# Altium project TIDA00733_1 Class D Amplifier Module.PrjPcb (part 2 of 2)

## Sheet TIDA00733_1 Class D Amp Sheet 6.SchDoc
size 431 x 279 mm; Date: Not shown in title block; ApprovedBy: Not shown in title block; CheckedBy: Not shown in title block; Author: Not shown in title block; CompanyName: Not shown in title block; Engineer: Not shown in title block; Organization: Not shown in title block; Address1: Not shown in title block; Address2: Not shown in title block; Address3: Not shown in title block; Address4: Not shown in title block; DocumentNumber: 6; Revision: Use project parameter SCH_Rev; SheetNumber: 6; SheetTotal: 8; PageSetup: Record=PageOptions¦CenterHorizontal=True¦CenterVertical=True¦PrintScale=1.00¦XCorrection=1.00¦YCorrection=1.00¦PrintKind=0¦BorderSize=5000000¦LeftOffset=0¦BottomOffset=0¦Orientation=2¦PaperLength=1000¦PaperWidth=1000¦Scale=100¦PaperSource=15¦PrintQuality=600¦MediaType=1¦DitherType=10¦PaperKind=Letter¦PrintScaleMode=1
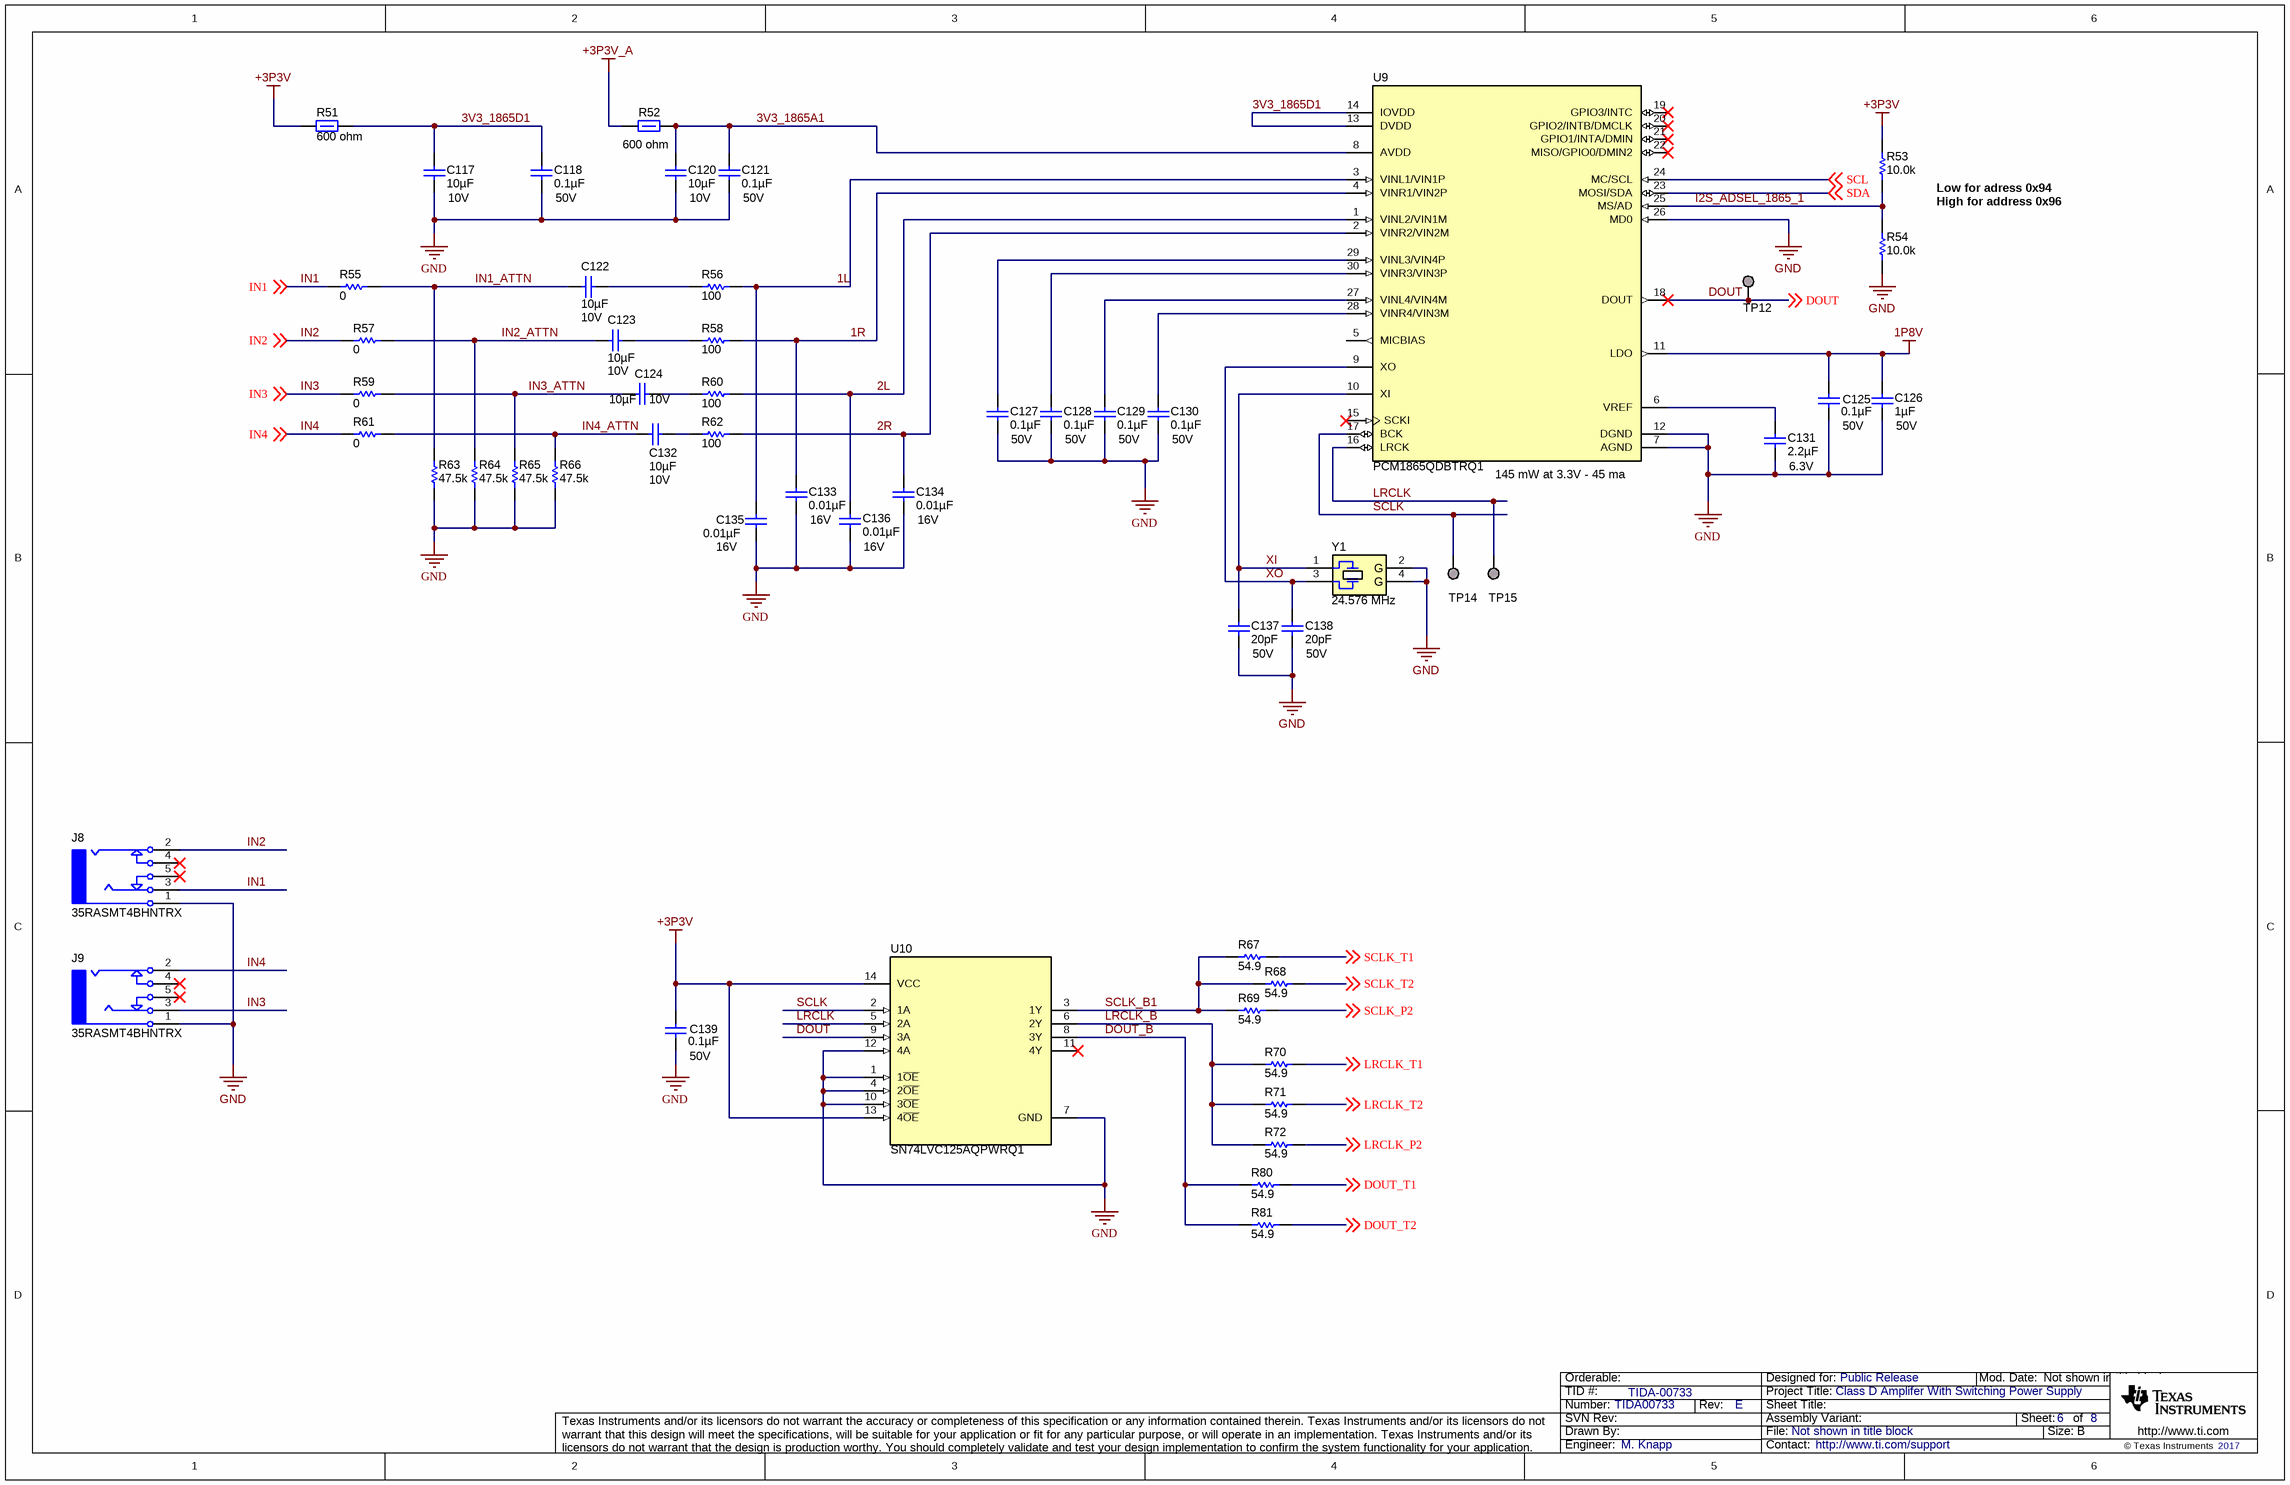
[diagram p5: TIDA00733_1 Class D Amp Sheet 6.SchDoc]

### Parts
C117  ValueDisplayed: 10µF  Value2: 10V  [0805L]  (hidden comment: GRM21BR71A106KE51L)
C118  ValueDisplayed: 0.1µF  Value2: 50V  [0402L]  (hidden comment: C1005X7R1H104K050BB)
C120  ValueDisplayed: 10µF  Value2: 10V  [0805L]  (hidden comment: GRM21BR71A106KE51L)
C121  ValueDisplayed: 0.1µF  Value2: 50V  [0402L]  (hidden comment: C1005X7R1H104K050BB)
C122  ValueDisplayed: 10µF  Value2: 10V  [0805L]  (hidden comment: GRM21BR71A106KE51L)
C123  ValueDisplayed: 10µF  Value2: 10V  [0805L]  (hidden comment: GRM21BR71A106KE51L)
C124  ValueDisplayed: 10µF  Value2: 10V  [0805L]  (hidden comment: GRM21BR71A106KE51L)
C125  ValueDisplayed: 0.1µF  Value2: 50V  [0402L]  (hidden comment: C1005X7R1H104K050BB)
C126  ValueDisplayed: 1µF  Value2: 50V  [0805L]  (hidden comment: GRM21BR71H105KA12L)
C127  ValueDisplayed: 0.1µF  Value2: 50V  [0402L]  (hidden comment: C1005X7R1H104K050BB)
C128  ValueDisplayed: 0.1µF  Value2: 50V  [0402L]  (hidden comment: C1005X7R1H104K050BB)
C129  ValueDisplayed: 0.1µF  Value2: 50V  [0402L]  (hidden comment: C1005X7R1H104K050BB)
C130  ValueDisplayed: 0.1µF  Value2: 50V  [0402L]  (hidden comment: C1005X7R1H104K050BB)
C131  ValueDisplayed: 2.2µF  Value2: 6.3V  [0603L]  (hidden comment: GCM188R70J225KE22D)
C132  ValueDisplayed: 10µF  Value2: 10V  [0805L]  (hidden comment: GRM21BR71A106KE51L)
C133  ValueDisplayed: 0.01µF  Value2: 16V  [0402L]  (hidden comment: 885012205031)
C134  ValueDisplayed: 0.01µF  Value2: 16V  [0402L]  (hidden comment: 885012205031)
C135  ValueDisplayed: 0.01µF  Value2: 16V  [0402L]  (hidden comment: 885012205031)
C136  ValueDisplayed: 0.01µF  Value2: 16V  [0402L]  (hidden comment: 885012205031)
C137  ValueDisplayed: 20pF  Value2: 50V  [0402L]  (hidden comment: GRM1555C1H200JA01D)
C138  ValueDisplayed: 20pF  Value2: 50V  [0402L]  (hidden comment: GRM1555C1H200JA01D)
C139  ValueDisplayed: 0.1µF  Value2: 50V  [0402L]  (hidden comment: C1005X7R1H104K050BB)
J8  35RASMT4BHNTRX  [Switchcraft_35RASM]
J9  35RASMT4BHNTRX  [Switchcraft_35RASM]
R51  ValueDisplayed: 600 ohm  [0402L]  (hidden comment: BLM15AX601SN1D)
R52  ValueDisplayed: 600 ohm  [0402L]  (hidden comment: BLM15AX601SN1D)
R53  ValueDisplayed: 10.0k  [0402L]  (hidden comment: CRCW040210K0FKED)
R54  ValueDisplayed: 10.0k  [0402L]  (hidden comment: CRCW040210K0FKED)
R55  ValueDisplayed: 0  [0402L]  (hidden comment: CRCW04020000Z0ED)
R56  ValueDisplayed: 100  [0402L]  (hidden comment: CRCW0402100RFKED)
R57  ValueDisplayed: 0  [0402L]  (hidden comment: CRCW04020000Z0ED)
R58  ValueDisplayed: 100  [0402L]  (hidden comment: CRCW0402100RFKED)
R59  ValueDisplayed: 0  [0402L]  (hidden comment: CRCW04020000Z0ED)
R60  ValueDisplayed: 100  [0402L]  (hidden comment: CRCW0402100RFKED)
R61  ValueDisplayed: 0  [0402L]  (hidden comment: CRCW04020000Z0ED)
R62  ValueDisplayed: 100  [0402L]  (hidden comment: CRCW0402100RFKED)
R63  ValueDisplayed: 47.5k  [0402L]  (hidden comment: CRCW040247K5FKED)
R64  ValueDisplayed: 47.5k  [0402L]  (hidden comment: CRCW040247K5FKED)
R65  ValueDisplayed: 47.5k  [0402L]  (hidden comment: CRCW040247K5FKED)
R66  ValueDisplayed: 47.5k  [0402L]  (hidden comment: CRCW040247K5FKED)
R67  ValueDisplayed: 54.9  [0402L]  (hidden comment: CRCW040254R9FKED)
R68  ValueDisplayed: 54.9  [0402L]  (hidden comment: CRCW040254R9FKED)
R69  ValueDisplayed: 54.9  [0402L]  (hidden comment: CRCW040254R9FKED)
R70  ValueDisplayed: 54.9  [0402L]  (hidden comment: CRCW040254R9FKED)
R71  ValueDisplayed: 54.9  [0402L]  (hidden comment: CRCW040254R9FKED)
R72  ValueDisplayed: 54.9  [0402L]  (hidden comment: CRCW040254R9FKED)
R80  ValueDisplayed: 54.9  [0402L]  (hidden comment: CRCW040254R9FKED)
R81  ValueDisplayed: 54.9  [0402L]  (hidden comment: CRCW040254R9FKED)
TP12  TESTPOINT  [PAD_1MM_SQUARE]  (value not drawn)  (no BOM)
TP14  TESTPOINT  [PAD_1MM_SQUARE]  (value not drawn)  (no BOM)
TP15  TESTPOINT  [PAD_1MM_SQUARE]  (value not drawn)  (no BOM)
U9  PCM1865QDBTRQ1  [DBT0030A_N]
U10  SN74LVC125AQPWRQ1  [PW0014A_N]
Y1  Frequency_Fixed: 24.576 MHz  [Abracon_ABM10AIG]  (hidden comment: ABM10AIG-24.576MHZ-J4Z-T3)

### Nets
1P8V: C125.1 C126.1 U9.11(LDO)
+3P3V: C139.1 R51.2 R53.2 U10.13(4~{OE}) U10.14(VCC)
+3P3V_A: R52.2
GND: C117.2 C118.2 C120.2 C121.2 C125.2 C126.2 C127.2 C128.2 C129.2 C130.2 C131.2 C133.2 C134.2 C135.2 C136.2 C137.2 C138.2 C139.2 J8.1(SLEEVE) J9.1(SLEEVE) R54.1 R63.1 R64.1 R65.1 R66.1 U9.7(AGND) U9.12(DGND) U9.26(MD0) U10.1(1~{OE}) U10.4(2~{OE}) U10.7(GND) U10.10(3~{OE}) U10.12(4A) Y1.2(GND) Y1.4(GND)
1L: C135.1 R56.2 U9.3(VINL1/VIN1P)
1R: C133.1 R58.2 U9.4(VINR1/VIN2P)
2L: C136.1 R60.2 U9.1(VINL2/VIN1M)
2R: C134.1 R62.2 U9.2(VINR2/VIN2M)
3V3_1865A1: C120.1 C121.1 R52.1 U9.8(AVDD)
3V3_1865D1: C117.1 C118.1 R51.1 U9.13(DVDD) U9.14(IOVDD)
DOUT: TP12.1 U9.18(DOUT) U10.9(3A) ; off-sheet DOUT
DOUT_B: R80.1 R81.1 U10.8(3Y)
DOUT_T1: R80.2 ; off-sheet DOUT_T1
DOUT_T2: R81.2 ; off-sheet DOUT_T2
I2S_ADSEL_1865_1: R53.1 R54.2 U9.25(MS/AD)
IN1: J8.3(TIP) R55.2 ; off-sheet IN1
IN1_ATTN: C122.1 R55.1 R63.2
IN2: J8.2(RING) R57.2 ; off-sheet IN2
IN2_ATTN: C123.1 R57.1 R64.2
IN3: J9.3(TIP) R59.2 ; off-sheet IN3
IN3_ATTN: C124.1 R59.1 R65.2
IN4: J9.2(RING) R61.2 ; off-sheet IN4
IN4_ATTN: C132.1 R61.1 R66.2
LRCLK: TP15.1 U9.16(LRCK) U10.5(2A)
LRCLK_B: R70.1 R71.1 R72.1 U10.6(2Y)
LRCLK_P2: R72.2 ; off-sheet LRCLK_P2
LRCLK_T1: R70.2 ; off-sheet LRCLK_T1
LRCLK_T2: R71.2 ; off-sheet LRCLK_T2
SCL: U9.24(MC/SCL) ; off-sheet SCL
SCLK: TP14.1 U9.17(BCK) U10.2(1A)
SCLK_B1: R67.1 R68.1 R69.1 U10.3(1Y)
SCLK_P2: R69.2 ; off-sheet SCLK_P2
SCLK_T1: R67.2 ; off-sheet SCLK_T1
SCLK_T2: R68.2 ; off-sheet SCLK_T2
SDA: U9.23(MOSI/SDA) ; off-sheet SDA
XI: C137.1 U9.10(XI) Y1.1
XO: C138.1 U9.9(XO) Y1.3
NetC122_2: C122.2 R56.1
NetC123_2: C123.2 R58.1
NetC124_2: C124.2 R60.1
NetC127_1: C127.1 U9.29(VINL3/VIN4P)
NetC128_1: C128.1 U9.30(VINR3/VIN3P)
NetC129_1: C129.1 U9.27(VINL4/VIN4M)
NetC130_1: C130.1 U9.28(VINR4/VIN3M)
NetC131_1: C131.1 U9.6(VREF)
NetC132_2: C132.2 R62.1

Not connected (* = marked no-connect by the designer): J8 4(RING_SWITCH)* 5(TIP_SWITCH)*; J9 4(RING_SWITCH)* 5(TIP_SWITCH)*; U9 5(MICBIAS) 15(SCKI)* 19(GPIO3/INTC)* 20(GPIO2/INTB/DMCLK)* 21(GPIO1/INTA/DMIN)* 22(MISO/GPIO0/DMIN2)*; U10 11(4Y)*

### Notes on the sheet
- Low for adress 0x94
  High for address 0x96
- (near U9) 145 mW at 3.3V - 45 ma

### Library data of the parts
C117 C120 C122-C124 C132 = GRM21BR71A106KE51L: CAP, CERM, 10 µF, 10 V, +/- 10%, X7R, 0805; Manufacturer: MuRata; Polarized: N; CompType: Capacitor; Value: 10uF; U/M: EA; Cap_F: 0.00001; Tolerance_%: 10; ESR_ohm: 0.003; Value1: 0.003 ohm; TaMin_C: -55; TaMax_C: 125; Cap_Case: 0805; AEC Category: Q200; SizeArea_mm2: 2.5; SizeAreaWB_mm2: 6.75; SizeX_mm: 2; SizeY_mm: 1.25; SizeZ_mm: 1.45
C118 C121 C125 C127-C130 C139 = C1005X7R1H104K050BB: CAP, CERM, 0.1 µF, 50 V, +/- 10%, X7R, 0402; Manufacturer: TDK; Polarized: N; CompType: Capacitor; Value: 0.1uF; U/M: EA; Cap_F: 0.0000001; Tolerance_%: 10; ESR_ohm: 0.039064; Value1: 0.039064 ohm; VDC_V: 50; IRMS_A: 0.814669; TaMin_C: -55; TaMax_C: 125; Cap_Case: 0402; AEC Category: Q200; SizeArea_mm2: 0.5; SizeAreaWB_mm2: 3; SizeX_mm: 1; SizeZ_mm: 0.6
C126 = GRM21BR71H105KA12L: CAP, CERM, 1 µF, 50 V, +/- 10%, X7R, 0805; Manufacturer: MuRata; Polarized: N; CompType: Capacitor; Value: 1uF; U/M: EA; Cap_F: 0.000001; Tolerance_%: 10; Value1: Unknown; VDC_V: 50; TaMin_C: -55; TaMax_C: 125; Cap_Case: 0805; AEC Category: Q200; SizeArea_mm2: 2.5; SizeAreaWB_mm2: 6.75; SizeX_mm: 2; SizeY_mm: 1.25; SizeZ_mm: 1.45
C131 = GCM188R70J225KE22D: CAP, CERM, 2.2 µF, 6.3 V, +/- 10%, X7R, AEC-Q200 Grade 1, 0603; Manufacturer: MuRata; Polarized: N; CompType: Capacitor; Value: 2.2uF; U/M: EA; Cap_F: 0.0000022; Tolerance_%: 10; Value1: Unknown; VDC_V: 6.3; TaMin_C: -55; TaMax_C: 125; Cap_Case: 0603; AEC Category: Q200; AEC Qualified: Y; AEC Grade: 1; SizeArea_mm2: 1.28; SizeAreaWB_mm2: 4.68; SizeX_mm: 1.6; SizeY_mm: 0.8
C133-C136 = 885012205031: CAP, CERM, 0.01 µF, 16 V, +/- 10%, X7R, 0402; Manufacturer: Wurth Elektronik; Polarized: N; CompType: Capacitor; Value: 0.01uF; U/M: EA; Cap_F: 0.00000001; Tolerance_%: 10; Value1: Unknown; VDC_V: 16; TaMin_C: -55; TaMax_C: 125; Cap_Case: 0402; AEC Category: Q200; SizeArea_mm2: 0.5; SizeAreaWB_mm2: 3; SizeX_mm: 1; SizeZ_mm: 0.6
C137 C138 = GRM1555C1H200JA01D: CAP, CERM, 20 pF, 50 V, +/- 5%, C0G/NP0, 0402; Manufacturer: MuRata; Polarized: N; CompType: Capacitor; Value: 20pF; U/M: EA; Cap_F: 0.00000000002; Tolerance_%: 5; Value1: Unknown; VDC_V: 50; TaMin_C: -55; TaMax_C: 125; Cap_Case: 0402; AEC Category: Q200; SizeArea_mm2: 0.5; SizeAreaWB_mm2: 3; SizeX_mm: 1; SizeZ_mm: 0.6
J8 J9 = 35RASMT4BHNTRX: Audio Jack, 3.5mm, Stereo, R/A, SMT; Manufacturer: Switchcraft; SymbolCreator: x0208326
R51 R52 = BLM15AX601SN1D: Ferrite Bead, 600 ohm @ 100 MHz, 0.5 A, 0402; Manufacturer: MuRata; Value: 600 ohm; Value1: 0.34 ohm; Value2: 0.5A; SizeArea_mm2: 0.5; SizeX_mm: 1; SizeZ_mm: 0.6; DCR_ohm: 0.34; SizeAreaWB_mm2: 3; ZTyp@100MHz_Ohm: 600; Green_Lifecycle: Active; Green_REACh: Passed
R53 R54 = CRCW040210K0FKED: RES, 10.0 k, 1%, 0.063 W, 0402; Manufacturer: Vishay-Dale; CompType: Resistor; Value: 10.0k; Res_ohm: 10000; Value_Code: 10k0; Tolerance_%: 1; Power_W: 0.063; Value2: 0.063W; VDC_V: 50; TempCo: 100 ppm/C; EIA_Code: E96; U/M: EA; AEC Category: Q200; SizeArea_mm2: 0.5; SizeZ_mm: 0.6
R55 R57 R59 R61 = CRCW04020000Z0ED: RES, 0, 5%, 0.063 W, 0402; Manufacturer: Vishay-Dale; CompType: Resistor; Value: 0; Value_Code: 0000; Tolerance_%: 5; Power_W: 0.063; Value2: 0.063W; VDC_V: 50; TempCo: 200 ppm/C; EIA_Code: E24; U/M: EA; AEC Category: Q200; SizeArea_mm2: 0.5; SizeX_mm: 1; SizeZ_mm: 0.6
R56 R58 R60 R62 = CRCW0402100RFKED: RES, 100, 1%, 0.063 W, 0402; Manufacturer: Vishay-Dale; CompType: Resistor; Value: 100; Value_Code: 100R; Tolerance_%: 1; Power_W: 0.063; Value2: 0.063W; VDC_V: 50; TempCo: 100 ppm/C; EIA_Code: E96; U/M: EA; AEC Category: Q200; SizeArea_mm2: 0.5; SizeZ_mm: 0.6
R63-R66 = CRCW040247K5FKED: RES, 47.5 k, 1%, 0.063 W, 0402; Manufacturer: Vishay-Dale; CompType: Resistor; Value: 47.5k; Res_ohm: 47500; Value_Code: 47k5; Tolerance_%: 1; Power_W: 0.063; Value2: 0.063W; VDC_V: 50; TempCo: 100 ppm/C; EIA_Code: E96; U/M: EA; AEC Category: Q200; SizeArea_mm2: 0.5; SizeZ_mm: 0.6; Green_Lifecycle: Active; Green_REACh: Passed
R67-R72 R80 R81 = CRCW040254R9FKED: RES, 54.9, 1%, 0.063 W, 0402; Manufacturer: Vishay-Dale; CompType: Resistor; Value: 54.9; Value_Code: 54R9; Tolerance_%: 1; Power_W: 0.063; Value2: 0.063W; VDC_V: 50; TempCo: 100 ppm/C; EIA_Code: E96; U/M: EA; AEC Category: Q200; SizeArea_mm2: 0.5; SizeZ_mm: 0.6
TP12 TP14 TP15 = PAD_1MM_SQUARE: 1.0x1.0mm pad, square, SMD; Manufacturer: Any
U9 = PCM1865QDBTRQ1: 110 dB 4ch Audio ADCs With Universal Front End, DBT0030A; Manufacturer: Texas Instruments; SymbolCreator: Altium; CompType: IC; U/M: EA; SizeArea_mm2: 49.92; SizeAreaWB_mm2: 82.32; SizeX_mm: 6.4; SizeY_mm: 7.8; SizeZ_mm: 1.2
U10 = SN74LVC125AQPWRQ1: QUADRUPLE BUS BUFFER GATE WITH 3-STATE OUTPUTS, PW0014A; Manufacturer: Texas Instruments; SymbolCreator: a0799628; CompType: IC; U/M: EA; SizeArea_mm2: 32; SizeAreaWB_mm2: 58.8; SizeX_mm: 6.4; SizeY_mm: 5; SizeZ_mm: 1.2
Y1 = ABM10AIG-24.576MHZ-J4Z-T3: Crystal, 24.576 MHz,  SMD; Manufacturer: Abracon Corporation; SymbolCreator: a0412235; U/M: EA; TaMin_C: -40; TaMax_C: 105; Frequency Stability: ±50ppm

## Sheet TIDA00733_1 Class D Amp Sheet 7.SchDoc
size 431 x 279 mm; Date: Not shown in title block; ApprovedBy: Not shown in title block; CheckedBy: Not shown in title block; Author: Not shown in title block; CompanyName: Not shown in title block; Engineer: Not shown in title block; Organization: Not shown in title block; Address1: Not shown in title block; Address2: Not shown in title block; Address3: Not shown in title block; Address4: Not shown in title block; DocumentNumber: 7; Revision: Use project parameter SCH_Rev; SheetNumber: 7; SheetTotal: 8; PageSetup: Record=PageOptions¦CenterHorizontal=True¦CenterVertical=True¦PrintScale=1.00¦XCorrection=1.00¦YCorrection=1.00¦PrintKind=0¦BorderSize=5000000¦LeftOffset=0¦BottomOffset=0¦Orientation=2¦PaperLength=1000¦PaperWidth=1000¦Scale=100¦PaperSource=15¦PrintQuality=600¦MediaType=1¦DitherType=10¦PaperKind=Letter¦PrintScaleMode=1
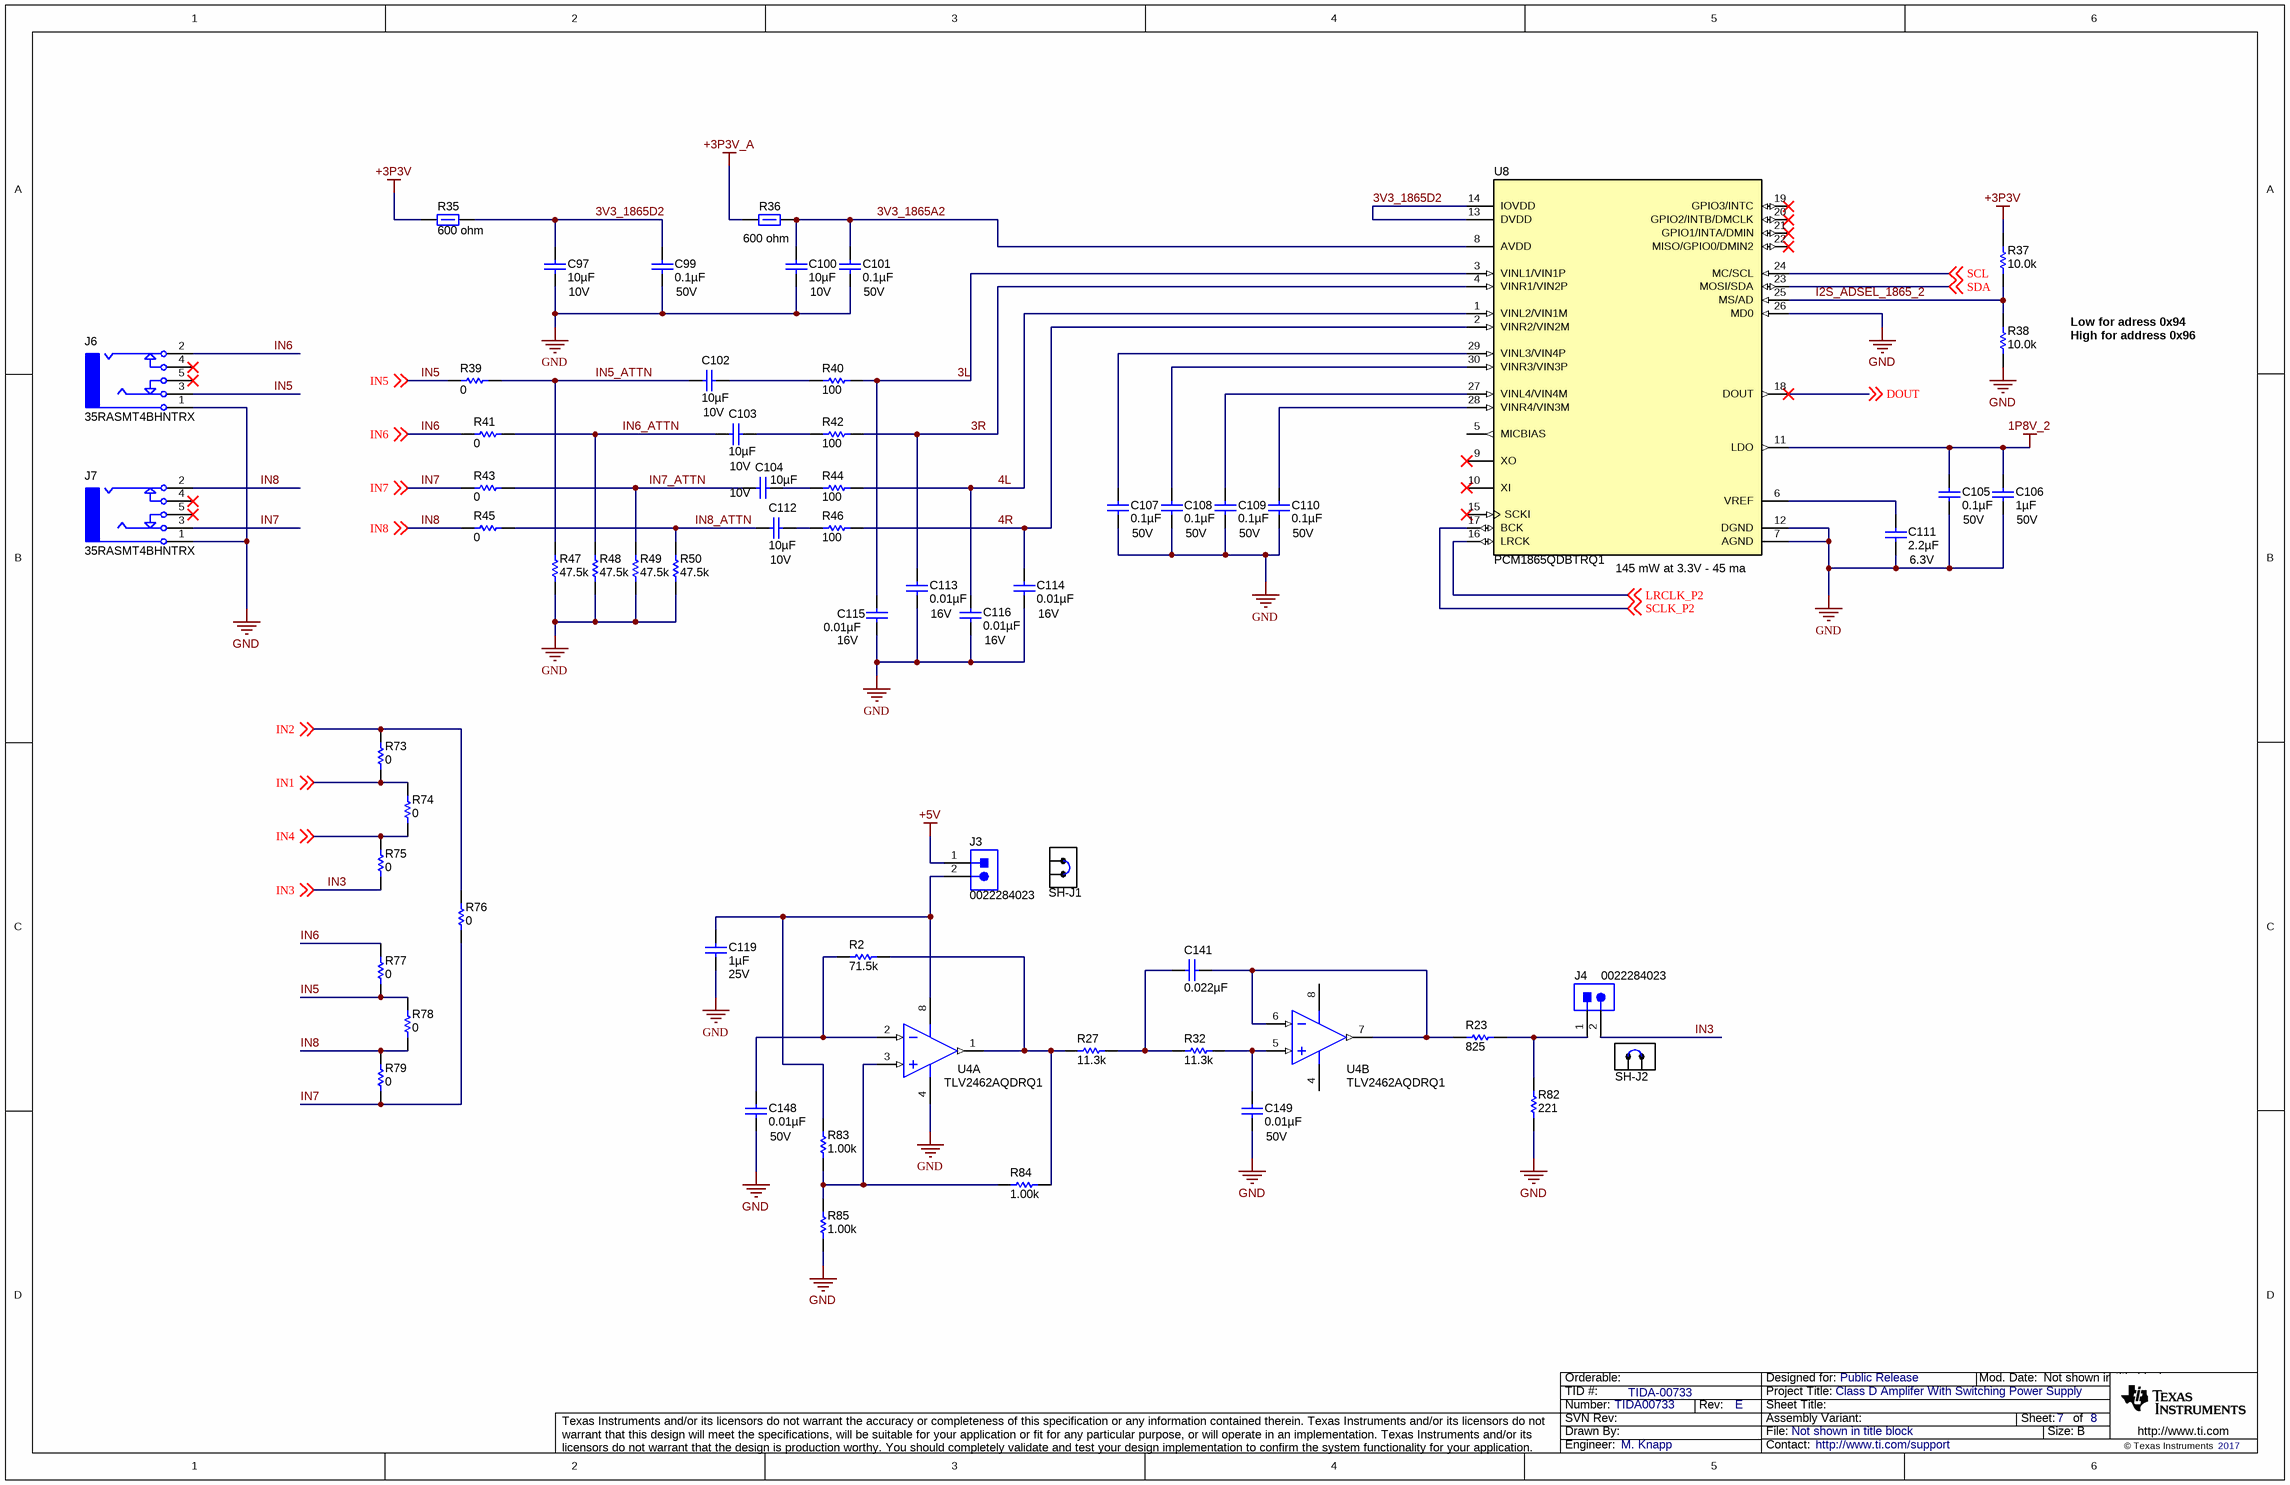
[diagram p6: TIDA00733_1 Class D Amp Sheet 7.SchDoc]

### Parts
C97  ValueDisplayed: 10µF  Value2: 10V  [0805L]  (hidden comment: GRM21BR71A106KE51L)
C99  ValueDisplayed: 0.1µF  Value2: 50V  [0402L]  (hidden comment: C1005X7R1H104K050BB)
C100  ValueDisplayed: 10µF  Value2: 10V  [0805L]  (hidden comment: GRM21BR71A106KE51L)
C101  ValueDisplayed: 0.1µF  Value2: 50V  [0402L]  (hidden comment: C1005X7R1H104K050BB)
C102  ValueDisplayed: 10µF  Value2: 10V  [0805L]  (hidden comment: GRM21BR71A106KE51L)
C103  ValueDisplayed: 10µF  Value2: 10V  [0805L]  (hidden comment: GRM21BR71A106KE51L)
C104  ValueDisplayed: 10µF  Value2: 10V  [0805L]  (hidden comment: GRM21BR71A106KE51L)
C105  ValueDisplayed: 0.1µF  Value2: 50V  [0402L]  (hidden comment: C1005X7R1H104K050BB)
C106  ValueDisplayed: 1µF  Value2: 50V  [0805L]  (hidden comment: GRM21BR71H105KA12L)
C107  ValueDisplayed: 0.1µF  Value2: 50V  [0402L]  (hidden comment: C1005X7R1H104K050BB)
C108  ValueDisplayed: 0.1µF  Value2: 50V  [0402L]  (hidden comment: C1005X7R1H104K050BB)
C109  ValueDisplayed: 0.1µF  Value2: 50V  [0402L]  (hidden comment: C1005X7R1H104K050BB)
C110  ValueDisplayed: 0.1µF  Value2: 50V  [0402L]  (hidden comment: C1005X7R1H104K050BB)
C111  ValueDisplayed: 2.2µF  Value2: 6.3V  [0603L]  (hidden comment: GCM188R70J225KE22D)
C112  ValueDisplayed: 10µF  Value2: 10V  [0805L]  (hidden comment: GRM21BR71A106KE51L)
C113  ValueDisplayed: 0.01µF  Value2: 16V  [0402L]  (hidden comment: 885012205031)
C114  ValueDisplayed: 0.01µF  Value2: 16V  [0402L]  (hidden comment: 885012205031)
C115  ValueDisplayed: 0.01µF  Value2: 16V  [0402L]  (hidden comment: 885012205031)
C116  ValueDisplayed: 0.01µF  Value2: 16V  [0402L]  (hidden comment: 885012205031)
C119  ValueDisplayed: 1µF  Value2: 25V  [0603L]  (hidden comment: C1608X7R1E105K080AB)
C141  ValueDisplayed: 0.022µF  [0402L]  (hidden comment: GRM155R71H223KA12D)
C148  ValueDisplayed: 0.01µF  Value2: 50V  [0402L]  (hidden comment: GCM155R71H103KA55D)
C149  ValueDisplayed: 0.01µF  Value2: 50V  [0402L]  (hidden comment: GCM155R71H103KA55D)
J3  0022284023  [Molex_0022284023]
J4  0022284023  [Molex_0022284023]
J6  35RASMT4BHNTRX  [Switchcraft_35RASM]
J7  35RASMT4BHNTRX  [Switchcraft_35RASM]
R2  ValueDisplayed: 71.5k  [0402L]  (hidden comment: CRCW040271K5FKED)
R23  ValueDisplayed: 825  [0402L]  (hidden comment: CRCW0402825RFKED)
R27  ValueDisplayed: 11.3k  [0402L]  (hidden comment: CRCW040211K3FKED)
R32  ValueDisplayed: 11.3k  [0402L]  (hidden comment: CRCW040211K3FKED)
R35  ValueDisplayed: 600 ohm  [0402L]  (hidden comment: BLM15AX601SN1D)
R36  ValueDisplayed: 600 ohm  [0402L]  (hidden comment: BLM15AX601SN1D)
R37  ValueDisplayed: 10.0k  [0402L]  (hidden comment: CRCW040210K0FKED)
R38  ValueDisplayed: 10.0k  [0402L]  (hidden comment: CRCW040210K0FKED)
R39  ValueDisplayed: 0  [0402L]  (hidden comment: CRCW04020000Z0ED)
R40  ValueDisplayed: 100  [0402L]  (hidden comment: CRCW0402100RFKED)
R41  ValueDisplayed: 0  [0402L]  (hidden comment: CRCW04020000Z0ED)
R42  ValueDisplayed: 100  [0402L]  (hidden comment: CRCW0402100RFKED)
R43  ValueDisplayed: 0  [0402L]  (hidden comment: CRCW04020000Z0ED)
R44  ValueDisplayed: 100  [0402L]  (hidden comment: CRCW0402100RFKED)
R45  ValueDisplayed: 0  [0402L]  (hidden comment: CRCW04020000Z0ED)
R46  ValueDisplayed: 100  [0402L]  (hidden comment: CRCW0402100RFKED)
R47  ValueDisplayed: 47.5k  [0402L]  (hidden comment: CRCW040247K5FKED)
R48  ValueDisplayed: 47.5k  [0402L]  (hidden comment: CRCW040247K5FKED)
R49  ValueDisplayed: 47.5k  [0402L]  (hidden comment: CRCW040247K5FKED)
R50  ValueDisplayed: 47.5k  [0402L]  (hidden comment: CRCW040247K5FKED)
R73  ValueDisplayed: 0  [0402L]  (hidden comment: CRCW04020000Z0ED)
R74  ValueDisplayed: 0  [0402L]  (hidden comment: CRCW04020000Z0ED)
R75  ValueDisplayed: 0  [0402L]  (hidden comment: CRCW04020000Z0ED)
R76  ValueDisplayed: 0  [0402L]  (hidden comment: CRCW04020000Z0ED)
R77  ValueDisplayed: 0  [0402L]  (hidden comment: CRCW04020000Z0ED)
R78  ValueDisplayed: 0  [0402L]  (hidden comment: CRCW04020000Z0ED)
R79  ValueDisplayed: 0  [0402L]  (hidden comment: CRCW04020000Z0ED)
R82  ValueDisplayed: 221  [0402L]  (hidden comment: CRCW0402221RFKED)
R83  ValueDisplayed: 1.00k  [0402L]  (hidden comment: CRCW04021K00FKED)
R84  ValueDisplayed: 1.00k  [0402L]  (hidden comment: CRCW04021K00FKED)
R85  ValueDisplayed: 1.00k  [0402L]  (hidden comment: CRCW04021K00FKED)
SH-J1  SPC02SYAN  [SPC02SYAN]  (value not drawn)  (mechanical)
SH-J2  SPC02SYAN  [SPC02SYAN]  (value not drawn)  (mechanical)
U4  TLV2462AQDRQ1  [D0008A_N]  (parts A,B of 2)
U8  PCM1865QDBTRQ1  [DBT0030A_N]

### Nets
1P8V_2: C105.1 C106.1 U8.11(LDO)
+3P3V: R35.2 R37.2
+3P3V_A: R36.2
+5V: J3.1
GND: C97.2 C99.2 C100.2 C101.2 C105.2 C106.2 C107.2 C108.2 C109.2 C110.2 C111.2 C113.2 C114.2 C115.2 C116.2 C119.2 C148.2 C149.2 J6.1(SLEEVE) J7.1(SLEEVE) R38.1 R47.1 R48.1 R49.1 R50.1 R82.1 R85.1 U4.4(GND) U8.7(AGND) U8.12(DGND) U8.26(MD0)
3L: C115.1 R40.2 U8.3(VINL1/VIN1P)
3R: C113.1 R42.2 U8.4(VINR1/VIN2P)
3V3_1865A2: C100.1 C101.1 R36.1 U8.8(AVDD)
3V3_1865D2: C97.1 C99.1 R35.1 U8.13(DVDD) U8.14(IOVDD)
4L: C116.1 R44.2 U8.1(VINL2/VIN1M)
4R: C114.1 R46.2 U8.2(VINR2/VIN2M)
DOUT: U8.18(DOUT) ; off-sheet DOUT
I2S_ADSEL_1865_2: R37.1 R38.2 U8.25(MS/AD)
IN1: R73.2 R74.2 ; off-sheet IN1
IN2: R73.1 R76.2 ; off-sheet IN2
IN3: J4.2 R75.2 ; off-sheet IN3
IN4: R74.1 R75.1 ; off-sheet IN4
IN5: J6.3(TIP) R39.2 R77.2 R78.2 ; off-sheet IN5
IN5_ATTN: C102.2 R39.1 R47.2
IN6: J6.2(RING) R41.2 R77.1 ; off-sheet IN6
IN6_ATTN: C103.2 R41.1 R48.2
IN7: J7.3(TIP) R43.2 R76.1 R79.2 ; off-sheet IN7
IN7_ATTN: C104.2 R43.1 R49.2
IN8: J7.2(RING) R45.2 R78.1 R79.1 ; off-sheet IN8
IN8_ATTN: C112.2 R45.1 R50.2
LRCLK_P2: U8.16(LRCK) ; off-sheet LRCLK_P2
SCL: U8.24(MC/SCL) ; off-sheet SCL
SCLK_P2: U8.17(BCK) ; off-sheet SCLK_P2
SDA: U8.23(MOSI/SDA) ; off-sheet SDA
NetC102_1: C102.1 R40.1
NetC103_1: C103.1 R42.1
NetC104_1: C104.1 R44.1
NetC107_1: C107.1 U8.29(VINL3/VIN4P)
NetC108_1: C108.1 U8.30(VINR3/VIN3P)
NetC109_1: C109.1 U8.27(VINL4/VIN4M)
NetC110_1: C110.1 U8.28(VINR4/VIN3M)
NetC111_1: C111.1 U8.6(VREF)
NetC112_1: C112.1 R46.1
NetC119_1: C119.1 J3.2 R83.2 U4.8(VDD+)
NetC141_1: C141.1 R23.1 U4.6(IN2-) U4.7(OUT2)
NetC141_2: C141.2 R27.2 R32.1
NetC148_1: C148.1 R2.1 U4.2(IN1-)
NetC149_1: C149.1 R32.2 U4.5(IN2+)
NetJ4_1: J4.1 R23.2 R82.2
NetR2_2: R2.2 R27.1 R84.2 U4.1(OUT1)
NetR83_1: R83.1 R84.1 R85.2 U4.3(IN1+)

Not connected (* = marked no-connect by the designer): J6 4(RING_SWITCH)* 5(TIP_SWITCH)*; J7 4(RING_SWITCH)* 5(TIP_SWITCH)*; U8 5(MICBIAS) 9(XO)* 10(XI)* 15(SCKI)* 19(GPIO3/INTC)* 20(GPIO2/INTB/DMCLK)* 21(GPIO1/INTA/DMIN)* 22(MISO/GPIO0/DMIN2)*

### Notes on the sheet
- Low for adress 0x94
  High for address 0x96
- (near U8) 145 mW at 3.3V - 45 ma

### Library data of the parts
C97 C100 C102-C104 C112 = GRM21BR71A106KE51L: as C117 on sheet TIDA00733_1 Class D Amp Sheet 6
C99 C101 C105 C107-C110 = C1005X7R1H104K050BB: as C118 on sheet TIDA00733_1 Class D Amp Sheet 6
C106 = GRM21BR71H105KA12L: as C126 on sheet TIDA00733_1 Class D Amp Sheet 6
C111 = GCM188R70J225KE22D: as C131 on sheet TIDA00733_1 Class D Amp Sheet 6
C113-C116 = 885012205031: as C133 on sheet TIDA00733_1 Class D Amp Sheet 6
C119 = C1608X7R1E105K080AB: CAP, CERM, 1 µF, 25 V, +/- 10%, X7R, 0603; Manufacturer: TDK; Polarized: N; CompType: Capacitor; Value: 1uF; U/M: EA; Cap_F: 0.000001; Tolerance_%: 10; Value1: Unknown; VDC_V: 25; TaMin_C: -55; TaMax_C: 125; Cap_Case: 0603; AEC Category: Q200; SizeArea_mm2: 1.28; SizeAreaWB_mm2: 4.68; SizeX_mm: 1.6; SizeY_mm: 0.8; SizeZ_mm: 1
C141 = GRM155R71H223KA12D: CAP, CERM, 0.022 µF, 50 V,+/- 10%, X7R, 0402; Manufacturer: MuRata; Polarized: N; CompType: Capacitor; Value: 0.022uF; U/M: EA; Cap_F: 0.000000022; Tolerance_%: 10; VDC_V: 50; Value2: 50V; TaMin_C: -55; TaMax_C: 125; Cap_Case: 0402; SizeArea_mm2: 0.5; SizeAreaWB_mm2: 3; SizeX_mm: 1; SizeZ_mm: 0.6; AEC Category: Q200; Green_Lifecycle: Active; Green_REACh: Passed
C148 C149 = GCM155R71H103KA55D: CAP, CERM, 0.01 µF, 50 V, +/- 10%, C0G/NP0, 0402; Manufacturer: MuRata; Polarized: N; CompType: Capacitor; Value: 0.01uF; U/M: EA; Cap_F: 0.00000001; Tolerance_%: 10; Value1: Unknown; VDC_V: 50; TaMin_C: -55; TaMax_C: 125; Cap_Case: 0402; AEC Category: Q200; SizeArea_mm2: 0.5; SizeAreaWB_mm2: 3; SizeX_mm: 1; SizeZ_mm: 0.6
J3 J4 = 0022284023: Header, 2.54mm, 2x1, Tin, TH; Manufacturer: Molex; SymbolCreator: a0412235; Pitch_mm: 2.54; Gender: Male; Shrouded: N; Row_Count: 1; Current_A: 4; Voltage_V: 250; Cert_UL: Y
J6 J7 = 35RASMT4BHNTRX: as J8 on sheet TIDA00733_1 Class D Amp Sheet 6
R2 = CRCW040271K5FKED: RES, 71.5 k, 1%, 0.063 W, 0402; Manufacturer: Vishay-Dale; CompType: Resistor; Value: 71.5k; Res_ohm: 71500; Value_Code: 71k5; Tolerance_%: 1; Power_W: 0.063; Value2: 0.063W; VDC_V: 50; TempCo: 100 ppm/C; SizeArea_mm2: 0.5; SizeZ_mm: 0.6; EIA_Code: E96; U/M: EA; AEC Category: Q200; Green_Lifecycle: Active; Green_REACh: Passed
R23 = CRCW0402825RFKED: RES, 825, 1%, 0.063 W, 0402; Manufacturer: Vishay-Dale; CompType: Resistor; Value: 825; Value_Code: 825R; Tolerance_%: 1; Power_W: 0.063; Value2: 0.063W; VDC_V: 50; TempCo: 100 ppm/C; SizeArea_mm2: 0.5; SizeZ_mm: 0.6; EIA_Code: E96; U/M: EA; AEC Category: Q200
R27 R32 = CRCW040211K3FKED: RES, 11.3 k, 1%, 0.063 W, 0402; Manufacturer: Vishay-Dale; CompType: Resistor; Value: 11.3k; Res_ohm: 11300; Value_Code: 11k3; Tolerance_%: 1; Power_W: 0.063; Value2: 0.063W; VDC_V: 50; TempCo: 100 ppm/C; SizeArea_mm2: 0.5; SizeZ_mm: 0.6; EIA_Code: E96; U/M: EA; AEC Category: Q200
R35 R36 = BLM15AX601SN1D: as R51 on sheet TIDA00733_1 Class D Amp Sheet 6
R37 R38 = CRCW040210K0FKED: as R53 on sheet TIDA00733_1 Class D Amp Sheet 6
R39 R41 R43 R45 R73-R79 = CRCW04020000Z0ED: as R55 on sheet TIDA00733_1 Class D Amp Sheet 6
R40 R42 R44 R46 = CRCW0402100RFKED: as R56 on sheet TIDA00733_1 Class D Amp Sheet 6
R47-R50 = CRCW040247K5FKED: as R63 on sheet TIDA00733_1 Class D Amp Sheet 6
R82 = CRCW0402221RFKED: RES, 221, 1%, 0.063 W, 0402; Manufacturer: Vishay-Dale; CompType: Resistor; Value: 221; Value_Code: 221R; Tolerance_%: 1; Power_W: 0.063; Value2: 0.063W; VDC_V: 50; TempCo: 100 ppm/C; SizeArea_mm2: 0.5; SizeZ_mm: 0.6; EIA_Code: E96; U/M: EA; AEC Category: Q200; Green_Lifecycle: Active; Green_REACh: Passed
R83-R85 = CRCW04021K00FKED: RES, 1.00 k, 1%, 0.063 W, 0402; Manufacturer: Vishay-Dale; CompType: Resistor; Value: 1.00k; Res_ohm: 1000; Value_Code: 1k00; Tolerance_%: 1; Power_W: 0.063; Value2: 0.063W; VDC_V: 50; TempCo: 100 ppm/C; SizeArea_mm2: 0.5; SizeZ_mm: 0.6; EIA_Code: E96; U/M: EA; AEC Category: Q200; Green_Lifecycle: Active; Green_REACh: Passed
SH-J1 SH-J2 = SPC02SYAN: Shunt, 100mil, Flash Gold, Black; Manufacturer: Sullins Connector Solutions; Value: 1x2; Note: You can "mate" this to a header by matching the designator.  i.e. use SH-J3 for header J3; Green_Lifecycle: Active; Green_REACh: Passed
U4 = TLV2462AQDRQ1: Automotive Catalog Low-Power Rail-to-Rail Input / Output Operational Amplifier with Shutdown, 2.7 to 6 V, -40 to 125 degC, 8-pin SOIC (D0008A), Green (RoHS & no Sb/Br); Manufacturer: Texas Instruments; Alternate PartNumber: Equivalent; CMRR(Min)(dB): 66; IIB(Max)(pA): 14; Iq per channel(Max)(mA): 0.575; Number of Channels: 2; Slew Rate(Typ)(V/us): 1.6; Sub Family: High Output Current Amplifier (>=50mA), Low Supply Voltage Amplifier (<=2.7V), Precision Amplifier; Total Supply Voltage(Max)(+5V is 5, +/-5V is 10): 6; Total Supply Voltage(Min)(+5V is 5, +/-5V is 10): 2.7; Vio (25C)(Max)(mV): 1.5; Vn at 1kHz(Typ)(nV/rtHz): 11
U8 = PCM1865QDBTRQ1: as U9 on sheet TIDA00733_1 Class D Amp Sheet 6

## Sheet TIDA00733_1 Class D Amp Sheet 8.SchDoc
size 431 x 279 mm; Date: Not shown in title block; ApprovedBy: Not shown in title block; CheckedBy: Not shown in title block; Author: Not shown in title block; CompanyName: Not shown in title block; Engineer: Not shown in title block; Organization: Not shown in title block; Address1: Not shown in title block; Address2: Not shown in title block; Address3: Not shown in title block; Address4: Not shown in title block; DocumentNumber: 8; Revision: Use project parameter SCH_Rev; SheetNumber: 8; SheetTotal: 8; PageSetup: Record=PageOptions¦CenterHorizontal=True¦CenterVertical=True¦PrintScale=1.00¦XCorrection=1.00¦YCorrection=1.00¦PrintKind=0¦BorderSize=5000000¦LeftOffset=0¦BottomOffset=0¦Orientation=2¦PaperLength=1000¦PaperWidth=1000¦Scale=100¦PaperSource=15¦PrintQuality=600¦MediaType=1¦DitherType=10¦PaperKind=Letter¦PrintScaleMode=1
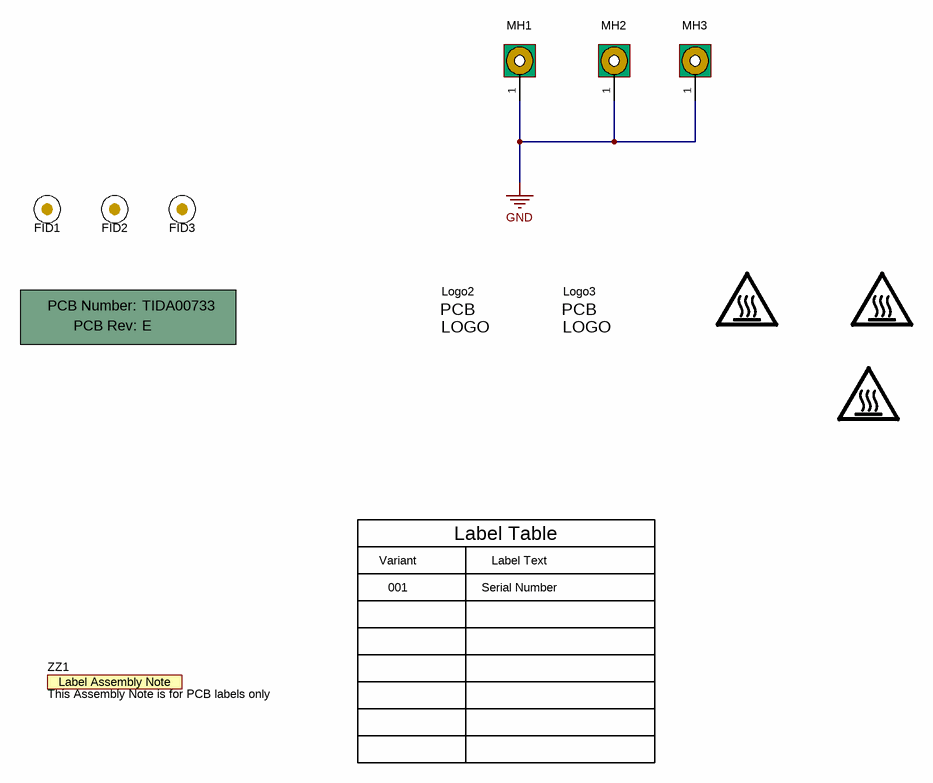
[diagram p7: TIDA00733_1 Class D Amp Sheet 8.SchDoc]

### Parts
!PCB1  Printed Circuit Board  (value not drawn)  (mechanical)
FID1  Fiducial  [Fiducial10-30]  (value not drawn)
FID2  Fiducial  [Fiducial10-30]  (value not drawn)
FID3  Fiducial  [Fiducial10-30]  (value not drawn)
LOGO1  CAUTION HOT SURFACE  [IEC_HotSurface_Medium]  (value not drawn)  (no BOM)
Logo2  Pb-Free Symbol  [Pb-Free_Overlay_Medium]  (value not drawn)  (no BOM)
Logo3  FCC disclaimer  [FCC_disclaimer]  (value not drawn)  (no BOM)
LOGO4  CAUTION HOT SURFACE  [IEC_HotSurface_Medium]  (value not drawn)  (no BOM)
LOGO6  CAUTION HOT SURFACE  [IEC_HotSurface_Medium]  (value not drawn)  (no BOM)
MH1  MTG_Pads  [MTGP_4-40_PanHead]  (value not drawn)  (no BOM)
MH2  MTG_Pads  [MTGP_4-40_PanHead]  (value not drawn)  (no BOM)
MH3  MTG_Pads  [MTGP_4-40_PanHead]  (value not drawn)  (no BOM)
ZZ1  This Assembly Note is for PCB labels only  [AssemblyNoteLabel]  (no BOM)

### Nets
GND: MH1.1 MH2.1 MH3.1

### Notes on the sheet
- Variant
- Label Table
- Label Text
- 001
- Serial Number

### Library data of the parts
!PCB1 = PCB: Manufacturer: Any; PartNumber: TIDA00733; SymbolCreator: a0412235
FID1-FID3 = Fiducial: Fiducial mark.  There is nothing to buy or mount.; SymbolCreator: codlsc
LOGO1 LOGO4 LOGO6 = IEC_HotSurface: IEC 61010-1 Hot Surface Warning; SymbolCreator: a0412235
Logo2 = Pb-Free: SymbolCreator: a0412235
Logo3 = FCC_disclaimer: SymbolCreator: a0412235
MH1-MH3 = Mounting Hole (Imperial) with Pads: PCB Mounting Hole; Manufacturer: Any; SymbolCreator: a0412235
ZZ1 = AssemblyNoteLabel: SymbolCreator: a0412235

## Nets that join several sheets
+3P3V: TIDA00733_1 Class D Amp Sheet 2 (8 pins), TIDA00733_1 Class D Amp Sheet 3 (C55.1 R14.1 R16.1 U2.19), TIDA00733_1 Class D Amp Sheet 4 (R19.2 R21.2), TIDA00733_1 Class D Amp Sheet 5 (6 pins), TIDA00733_1 Class D Amp Sheet 6 (5 pins), TIDA00733_1 Class D Amp Sheet 7 (R35.2 R37.2)
+3P3V_A: TIDA00733_1 Class D Amp Sheet 4 (C143.1 R21.1 U5.5), TIDA00733_1 Class D Amp Sheet 6 (R52.2), TIDA00733_1 Class D Amp Sheet 7 (R36.2)
+5V: TIDA00733_1 Class D Amp Sheet 4 (15 pins), TIDA00733_1 Class D Amp Sheet 7 (J3.1)
GND: TIDA00733_1 Class D Amp Sheet 2 (42 pins), TIDA00733_1 Class D Amp Sheet 3 (42 pins), TIDA00733_1 Class D Amp Sheet 4 (41 pins), TIDA00733_1 Class D Amp Sheet 5 (7 pins), TIDA00733_1 Class D Amp Sheet 6 (35 pins), TIDA00733_1 Class D Amp Sheet 7 (31 pins), TIDA00733_1 Class D Amp Sheet 8 (MH1.1 MH2.1 MH3.1)
PVDD: TIDA00733_1 Class D Amp Sheet 2 (16 pins), TIDA00733_1 Class D Amp Sheet 3 (16 pins), TIDA00733_1 Class D Amp Sheet 4 (20 pins)
DOUT: TIDA00733_1 Class D Amp Sheet 6 (TP12.1 U9.18 U10.9), TIDA00733_1 Class D Amp Sheet 7 (U8.18)
DOUT_T1: TIDA00733_1 Class D Amp Sheet 2 (U1.15), TIDA00733_1 Class D Amp Sheet 6 (R80.2)
DOUT_T2: TIDA00733_1 Class D Amp Sheet 3 (U2.15), TIDA00733_1 Class D Amp Sheet 6 (R81.2)
IN1: TIDA00733_1 Class D Amp Sheet 6 (J8.3 R55.2), TIDA00733_1 Class D Amp Sheet 7 (R73.2 R74.2)
IN2: TIDA00733_1 Class D Amp Sheet 6 (J8.2 R57.2), TIDA00733_1 Class D Amp Sheet 7 (R73.1 R76.2)
IN3: TIDA00733_1 Class D Amp Sheet 6 (J9.3 R59.2), TIDA00733_1 Class D Amp Sheet 7 (J4.2 R75.2)
IN4: TIDA00733_1 Class D Amp Sheet 6 (J9.2 R61.2), TIDA00733_1 Class D Amp Sheet 7 (R74.1 R75.1)
LRCLK_P2: TIDA00733_1 Class D Amp Sheet 6 (R72.2), TIDA00733_1 Class D Amp Sheet 7 (U8.16)
LRCLK_T1: TIDA00733_1 Class D Amp Sheet 2 (U1.14), TIDA00733_1 Class D Amp Sheet 6 (R70.2)
LRCLK_T2: TIDA00733_1 Class D Amp Sheet 3 (U2.14), TIDA00733_1 Class D Amp Sheet 6 (R71.2)
nFAULT: TIDA00733_1 Class D Amp Sheet 2 (D1.1 U1.26), TIDA00733_1 Class D Amp Sheet 3 (U2.26), TIDA00733_1 Class D Amp Sheet 5 (U7.8)
nMUTE: TIDA00733_1 Class D Amp Sheet 2 (R5.1 U1.25), TIDA00733_1 Class D Amp Sheet 3 (U2.25)
nRESET_PS: TIDA00733_1 Class D Amp Sheet 4 (U3.19), TIDA00733_1 Class D Amp Sheet 5 (R34.1)
nSTANDBY: TIDA00733_1 Class D Amp Sheet 2 (R6.1 U1.24), TIDA00733_1 Class D Amp Sheet 3 (U2.24)
nWARN: TIDA00733_1 Class D Amp Sheet 2 (D2.1 U1.27), TIDA00733_1 Class D Amp Sheet 3 (U2.27), TIDA00733_1 Class D Amp Sheet 5 (U7.9)
PS_SYNC: TIDA00733_1 Class D Amp Sheet 4 (R20.2 U3.3), TIDA00733_1 Class D Amp Sheet 5 (U7.6)
SCL: TIDA00733_1 Class D Amp Sheet 2 (U1.20), TIDA00733_1 Class D Amp Sheet 3 (U2.20), TIDA00733_1 Class D Amp Sheet 5 (R29.1 TP7.1 U7.14), TIDA00733_1 Class D Amp Sheet 6 (U9.24), TIDA00733_1 Class D Amp Sheet 7 (U8.24)
SCLK_P2: TIDA00733_1 Class D Amp Sheet 6 (R69.2), TIDA00733_1 Class D Amp Sheet 7 (U8.17)
SCLK_T1: TIDA00733_1 Class D Amp Sheet 2 (U1.12 U1.13), TIDA00733_1 Class D Amp Sheet 6 (R67.2)
SCLK_T2: TIDA00733_1 Class D Amp Sheet 3 (U2.12 U2.13), TIDA00733_1 Class D Amp Sheet 6 (R68.2)
SDA: TIDA00733_1 Class D Amp Sheet 2 (U1.21), TIDA00733_1 Class D Amp Sheet 3 (U2.21), TIDA00733_1 Class D Amp Sheet 5 (R30.1 TP6.1 U7.15), TIDA00733_1 Class D Amp Sheet 6 (U9.23), TIDA00733_1 Class D Amp Sheet 7 (U8.23)

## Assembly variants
001: not fitted C83 C85 C88 C153 FID1 FID2 FID3 R4 R7 R11 R14 R16 R20 R21 R28 R31 R34 R38 R53 R73 R74 R75 R76 R77 R78 R79 U12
